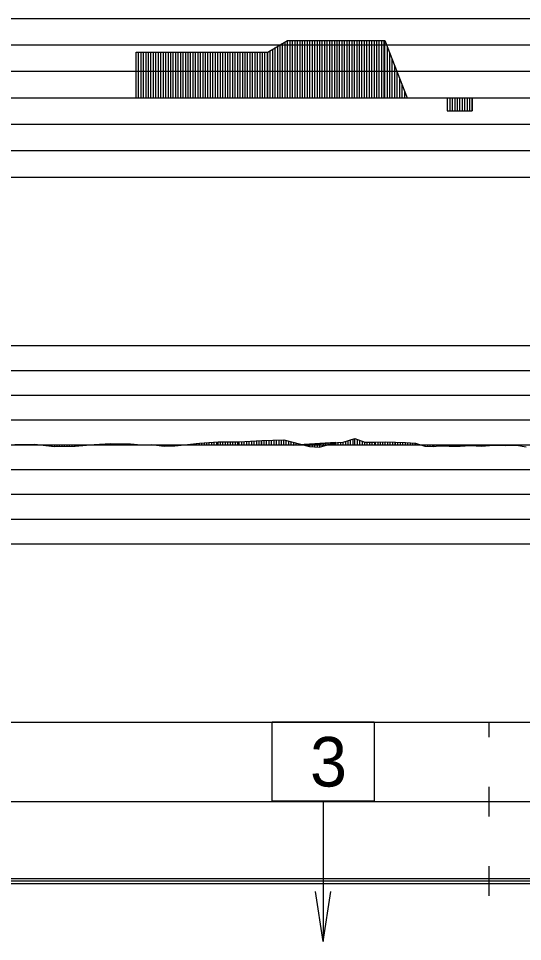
# Model space of a CAD drawing. Extents: x 2 to 10148, y 0 to 380.
# Drawn here: x 1050.8 to 1101.7, y 191.9 to 285 of the extents above; entities that cross this region are included whole.
import ezdxf

# ---------------------------------------------------------------- set-up
doc = ezdxf.new("R2010")
doc.units = 0
for name, color, linetype in [('POSUN_CARA', 7, 'Continuous'), ('POSUN_RASTR', 7, 'Continuous'), ('RYCHL_RASTR', 7, 'Continuous'), ('SLOUPEC', 7, 'Continuous'), ('ZRYCHL_CARA', 7, 'Continuous'), ('ZRYCHL_RASTR', 7, 'Continuous')]:
    doc.layers.add(name, color=color, linetype=linetype)

msp = doc.modelspace()

# ---------------------------------------------------------------- linework, layer by layer
at = {"layer": 'POSUN_CARA'}
for p, q in [((1058.427, 242.028), (1060.09, 242.109)), ((1060.09, 242.109), (1062.119, 242.076)), ((1060.09, 242), (1060.09, 242.109)), ((1060.34, 242), (1060.34, 242.105)), ((1067.549, 242.002), (1069.06, 242.171)), ((1068.549, 242), (1068.549, 242.114)), ((1068.799, 242), (1068.799, 242.142)), ((1069.049, 242), (1069.049, 242.169)), ((1069.06, 242.171), (1070.936, 242.302)), ((1069.06, 242), (1069.06, 242.171)), ((1069.31, 242), (1069.31, 242.188)), ((1069.56, 242), (1069.56, 242.206)), ((1069.81, 242), (1069.81, 242.223)), ((1070.06, 242), (1070.06, 242.241)), ((1070.31, 242), (1070.31, 242.258)), ((1070.56, 242), (1070.56, 242.276)), ((1070.81, 242), (1070.81, 242.293)), ((1070.936, 242.302), (1073.087, 242.304)), ((1070.936, 242), (1070.936, 242.302)), ((1071.186, 242), (1071.186, 242.302)), ((1071.436, 242), (1071.436, 242.302)), ((1071.686, 242), (1071.686, 242.303)), ((1071.936, 242), (1071.936, 242.303)), ((1072.186, 242), (1072.186, 242.303)), ((1072.436, 242), (1072.436, 242.303)), ((1072.686, 242), (1072.686, 242.303)), ((1072.936, 242), (1072.936, 242.304)), ((1073.087, 242.304), (1075.345, 242.428)), ((1073.087, 242), (1073.087, 242.304)), ((1073.337, 242), (1073.337, 242.317)), ((1073.587, 242), (1073.587, 242.331)), ((1073.837, 242), (1073.837, 242.345)), ((1074.087, 242), (1074.087, 242.359)), ((1074.337, 242), (1074.337, 242.373)), ((1074.587, 242), (1074.587, 242.386)), ((1074.837, 242), (1074.837, 242.4)), ((1075.087, 242), (1075.087, 242.414)), ((1075.337, 242), (1075.337, 242.428)), ((1075.345, 242.428), (1077.578, 242.487)), ((1075.345, 242), (1075.345, 242.428)), ((1075.595, 242), (1075.595, 242.435)), ((1075.845, 242), (1075.845, 242.441)), ((1076.095, 242), (1076.095, 242.448)), ((1076.345, 242), (1076.345, 242.454)), ((1076.595, 242), (1076.595, 242.461)), ((1076.845, 242), (1076.845, 242.467)), ((1077.095, 242), (1077.095, 242.474)), ((1077.345, 242), (1077.345, 242.48)), ((1077.578, 242.487), (1080.179, 241.816)), ((1077.578, 242), (1077.578, 242.487)), ((1077.828, 242), (1077.828, 242.422)), ((1078.078, 242), (1078.078, 242.358)), ((1078.328, 242), (1078.328, 242.293)), ((1078.565, 241.959), (1083.569, 242.267)), ((1082.838, 242.237), (1078.565, 241.959)), ((1078.578, 242), (1078.578, 242.229)), ((1078.828, 242), (1078.828, 242.164)), ((1081.065, 242), (1081.065, 242.113)), ((1081.185, 241.754), (1082.838, 242.237)), ((1081.315, 242), (1081.315, 242.128)), ((1081.565, 242), (1081.565, 242.143)), ((1081.815, 242), (1081.815, 242.159)), ((1082.065, 242), (1082.065, 242.174)), ((1082.315, 242), (1082.315, 242.189)), ((1082.435, 242), (1082.435, 242.12)), ((1082.565, 242), (1082.565, 242.205)), ((1082.685, 242), (1082.685, 242.193)), ((1082.815, 242), (1082.815, 242.22)), ((1083.065, 242), (1083.065, 242.236)), ((1083.315, 242), (1083.315, 242.251)), ((1083.565, 242), (1083.565, 242.266)), ((1083.569, 242.267), (1084.747, 242.614)), ((1083.569, 242), (1083.569, 242.267)), ((1083.819, 242), (1083.819, 242.34)), ((1084.069, 242), (1084.069, 242.414)), ((1084.319, 242), (1084.319, 242.487)), ((1084.569, 242), (1084.569, 242.561)), ((1084.747, 242.614), (1085.745, 242.252)), ((1084.747, 242), (1084.747, 242.614)), ((1084.997, 242), (1084.997, 242.523)), ((1085.247, 242), (1085.247, 242.432)), ((1085.497, 242), (1085.497, 242.342)), ((1085.745, 242.252), (1086.828, 242.251)), ((1085.745, 242), (1085.745, 242.252)), ((1085.995, 242), (1085.995, 242.252)), ((1086.245, 242), (1086.245, 242.251)), ((1086.495, 242), (1086.495, 242.251)), ((1086.745, 242), (1086.745, 242.251)), ((1086.828, 242.251), (1087.81, 242.304)), ((1086.828, 242), (1086.828, 242.251)), ((1087.078, 242), (1087.078, 242.265)), ((1087.328, 242), (1087.328, 242.278)), ((1087.578, 242), (1087.578, 242.292)), ((1087.81, 242.304), (1088.84, 242.271)), ((1087.81, 242), (1087.81, 242.304)), ((1088.06, 242), (1088.06, 242.296)), ((1088.31, 242), (1088.31, 242.288)), ((1088.56, 242), (1088.56, 242.28)), ((1088.81, 242), (1088.81, 242.272)), ((1088.84, 242.271), (1089.843, 242.214)), ((1088.84, 242), (1088.84, 242.271)), ((1089.09, 242), (1089.09, 242.257)), ((1089.34, 242), (1089.34, 242.242)), ((1089.59, 242), (1089.59, 242.228)), ((1089.84, 242), (1089.84, 242.214)), ((1089.843, 242.214), (1090.858, 242.156)), ((1089.843, 242), (1089.843, 242.214)), ((1090.093, 242), (1090.093, 242.2)), ((1090.343, 242), (1090.343, 242.185)), ((1090.593, 242), (1090.593, 242.171)), ((1090.843, 242), (1090.843, 242.157)), ((1090.858, 242.156), (1091.812, 241.847)), ((1090.858, 242), (1090.858, 242.156)), ((1050.431, 242.038), (1052.432, 242.05)), ((1050.931, 242), (1050.931, 242.041)), ((1051.181, 242), (1051.181, 242.043)), ((1051.431, 242), (1051.431, 242.044)), ((1051.681, 242), (1051.681, 242.046)), ((1051.931, 242), (1051.931, 242.047)), ((1052.181, 242), (1052.181, 242.049)), ((1052.431, 242), (1052.431, 242.05)), ((1052.432, 242.05), (1054.429, 241.808)), ((1052.432, 242), (1052.432, 242.05)), ((1052.682, 242), (1052.682, 242.02)), ((1052.932, 242), (1052.932, 241.989)), ((1053.182, 242), (1053.182, 241.959)), ((1053.432, 242), (1053.432, 241.929)), ((1053.682, 242), (1053.682, 241.898)), ((1053.932, 242), (1053.932, 241.868)), ((1054.182, 242), (1054.182, 241.838)), ((1054.429, 242), (1054.429, 241.808)), ((1054.429, 241.808), (1056.514, 241.855)), ((1054.679, 242), (1054.679, 241.813)), ((1054.929, 242), (1054.929, 241.819)), ((1055.179, 242), (1055.179, 241.825)), ((1055.429, 242), (1055.429, 241.83)), ((1055.679, 242), (1055.679, 241.836)), ((1055.929, 242), (1055.929, 241.842)), ((1056.179, 242), (1056.179, 241.847)), ((1056.429, 242), (1056.429, 241.853)), ((1056.514, 241.855), (1058.427, 242.028)), ((1056.514, 242), (1056.514, 241.855)), ((1056.764, 242), (1056.764, 241.877)), ((1057.014, 242), (1057.014, 241.9)), ((1057.264, 242), (1057.264, 241.923)), ((1057.514, 242), (1057.514, 241.945)), ((1057.764, 242), (1057.764, 241.968)), ((1058.014, 242), (1058.014, 241.991)), ((1058.264, 242), (1058.264, 242.014)), ((1058.427, 242), (1058.427, 242.028)), ((1058.677, 242), (1058.677, 242.04)), ((1058.927, 242), (1058.927, 242.052)), ((1059.177, 242), (1059.177, 242.065)), ((1059.427, 242), (1059.427, 242.077)), ((1059.677, 242), (1059.677, 242.089)), ((1059.927, 242), (1059.927, 242.101)), ((1060.59, 242), (1060.59, 242.101)), ((1060.84, 242), (1060.84, 242.097)), ((1061.09, 242), (1061.09, 242.093)), ((1061.34, 242), (1061.34, 242.089)), ((1061.59, 242), (1061.59, 242.085)), ((1061.84, 242), (1061.84, 242.081)), ((1062.09, 242), (1062.09, 242.077)), ((1062.119, 242.076), (1063.175, 241.999)), ((1062.119, 242), (1062.119, 242.076)), ((1062.369, 242), (1062.369, 242.058)), ((1062.619, 242), (1062.619, 242.04)), ((1062.869, 242), (1062.869, 242.022)), ((1063.119, 242), (1063.119, 242.004)), ((1063.175, 241.999), (1064.229, 242.037)), ((1063.175, 242), (1063.175, 241.999)), ((1063.425, 242), (1063.425, 242.008)), ((1063.675, 242), (1063.675, 242.017)), ((1063.925, 242), (1063.925, 242.026)), ((1064.175, 242), (1064.175, 242.035)), ((1064.229, 242.037), (1065.502, 241.849)), ((1064.229, 242), (1064.229, 242.037)), ((1064.479, 242), (1064.479, 242)), ((1064.729, 242), (1064.729, 241.963)), ((1064.979, 242), (1064.979, 241.926)), ((1065.229, 242), (1065.229, 241.889)), ((1065.479, 242), (1065.479, 241.852)), ((1065.502, 242), (1065.502, 241.849)), ((1065.502, 241.849), (1066.572, 241.882)), ((1065.752, 242), (1065.752, 241.856)), ((1066.002, 242), (1066.002, 241.864)), ((1066.252, 242), (1066.252, 241.872)), ((1066.502, 242), (1066.502, 241.88)), ((1066.572, 241.882), (1067.549, 242.002)), ((1066.572, 242), (1066.572, 241.882)), ((1066.822, 242), (1066.822, 241.913)), ((1067.072, 242), (1067.072, 241.944)), ((1067.322, 242), (1067.322, 241.974)), ((1067.549, 242), (1067.549, 242.002)), ((1067.799, 242), (1067.799, 242.03)), ((1068.049, 242), (1068.049, 242.058)), ((1068.299, 242), (1068.299, 242.086)), ((1078.565, 242), (1078.565, 241.959)), ((1078.815, 242), (1078.815, 241.974)), ((1079.065, 242), (1079.065, 241.99)), ((1079.078, 242), (1079.078, 242.1)), ((1079.315, 242), (1079.315, 242.005)), ((1079.328, 242), (1079.328, 242.035)), ((1079.565, 242), (1079.565, 242.02)), ((1079.578, 242), (1079.578, 241.971)), ((1079.815, 242), (1079.815, 242.036)), ((1079.828, 242), (1079.828, 241.906)), ((1080.065, 242), (1080.065, 242.051)), ((1080.078, 242), (1080.078, 241.842)), ((1080.179, 242), (1080.179, 241.816)), ((1080.179, 241.816), (1081.185, 241.754)), ((1080.315, 242), (1080.315, 242.067)), ((1080.429, 242), (1080.429, 241.8)), ((1080.565, 242), (1080.565, 242.082)), ((1080.679, 242), (1080.679, 241.785)), ((1080.815, 242), (1080.815, 242.097)), ((1080.929, 242), (1080.929, 241.77)), ((1081.179, 242), (1081.179, 241.755)), ((1081.185, 242), (1081.185, 241.754)), ((1081.435, 242), (1081.435, 241.827)), ((1081.685, 242), (1081.685, 241.9)), ((1081.935, 242), (1081.935, 241.974)), ((1082.185, 242), (1082.185, 242.047)), ((1091.108, 242), (1091.108, 242.075)), ((1091.358, 242), (1091.358, 241.994)), ((1091.608, 242), (1091.608, 241.913)), ((1091.812, 242), (1091.812, 241.847)), ((1091.812, 241.847), (1092.703, 241.806)), ((1092.062, 242), (1092.062, 241.836)), ((1092.312, 242), (1092.312, 241.824)), ((1092.562, 242), (1092.562, 241.813)), ((1092.703, 242), (1092.703, 241.806)), ((1092.703, 241.806), (1093.21, 241.884)), ((1092.953, 242), (1092.953, 241.845)), ((1093.203, 242), (1093.203, 241.883)), ((1093.21, 242), (1093.21, 241.884)), ((1093.21, 241.884), (1094.257, 241.861)), ((1093.46, 242), (1093.46, 241.879)), ((1093.71, 242), (1093.71, 241.873)), ((1093.96, 242), (1093.96, 241.867)), ((1094.21, 242), (1094.21, 241.862)), ((1094.257, 242), (1094.257, 241.861)), ((1094.257, 241.861), (1095.362, 241.838)), ((1094.507, 242), (1094.507, 241.855)), ((1094.757, 242), (1094.757, 241.85)), ((1095.007, 242), (1095.007, 241.845)), ((1095.257, 242), (1095.257, 241.84)), ((1095.362, 242), (1095.362, 241.838)), ((1095.362, 241.838), (1096.402, 241.924)), ((1095.612, 242), (1095.612, 241.858)), ((1095.862, 242), (1095.862, 241.879)), ((1096.112, 242), (1096.112, 241.9)), ((1096.362, 242), (1096.362, 241.921)), ((1096.402, 242), (1096.402, 241.924)), ((1096.402, 241.924), (1097.541, 241.856)), ((1096.652, 242), (1096.652, 241.909)), ((1096.902, 242), (1096.902, 241.894)), ((1097.152, 242), (1097.152, 241.879)), ((1097.402, 242), (1097.402, 241.865)), ((1097.541, 242), (1097.541, 241.856)), ((1097.541, 241.856), (1098.683, 241.944)), ((1097.791, 242), (1097.791, 241.875)), ((1098.041, 242), (1098.041, 241.895)), ((1098.291, 242), (1098.291, 241.914)), ((1098.541, 242), (1098.541, 241.933)), ((1098.683, 242), (1098.683, 241.944)), ((1098.683, 241.944), (1099.905, 241.931)), ((1098.933, 242), (1098.933, 241.941)), ((1099.183, 242), (1099.183, 241.939)), ((1099.433, 242), (1099.433, 241.936)), ((1099.683, 242), (1099.683, 241.934)), ((1099.905, 242), (1099.905, 241.931)), ((1099.905, 241.931), (1101.034, 241.948)), ((1100.155, 242), (1100.155, 241.935)), ((1100.405, 242), (1100.405, 241.939)), ((1100.655, 242), (1100.655, 241.943)), ((1100.905, 242), (1100.905, 241.946)), ((1101.034, 242), (1101.034, 241.948)), ((1101.034, 241.948), (1102.035, 241.788)), ((1101.284, 242), (1101.284, 241.908)), ((1101.534, 242), (1101.534, 241.868))]:
    msp.add_line(p, q, dxfattribs=at)
at = {"layer": 'POSUN_RASTR'}
for p, q in [((952, 252), (1148, 252)), ((952, 249.5), (1148, 249.5)), ((952, 247), (1148, 247)), ((952, 244.5), (1148, 244.5)), ((631.22, 242), (1245.395, 242)), ((952, 239.5), (1148, 239.5)), ((952, 237), (1148, 237)), ((952, 234.5), (1148, 234.5)), ((952, 232), (1148, 232))]:
    msp.add_line(p, q, dxfattribs=at)
at = {"layer": 'RYCHL_RASTR'}
for p, q in [((631.22, 214), (1245.395, 214)), ((1098.288, 212.5), (1098.288, 214)), ((1098.288, 204.5), (1098.288, 207.5)), ((631.22, 206), (1245.395, 206)), ((1098.288, 196.5), (1098.288, 199.5)), ((631.22, 198.25), (1245.395, 198.25)), ((631.22, 198), (1245.395, 198)), ((631.22, 197.75), (1245.395, 197.75))]:
    msp.add_line(p, q, dxfattribs=at)
at = {"layer": 'SLOUPEC'}
for p, q in [((1081.55, 206.034), (1081.55, 191.884)), ((1081.55, 191.884), (1080.783, 196.926)), ((1081.55, 191.884), (1082.318, 196.926))]:
    msp.add_line(p, q, dxfattribs=at)
msp.add_lwpolyline([(1076.404, 214.033), (1086.696, 214.033), (1086.696, 206.034), (1076.404, 206.034)], close=True, dxfattribs=at)
at = {"layer": 'ZRYCHL_CARA'}
for p, q in [((1075.959, 281.615), (1077.959, 282.791)), ((1076.959, 277), (1076.959, 282.203)), ((1077.209, 277), (1077.209, 282.35)), ((1077.459, 277), (1077.459, 282.497)), ((1077.709, 277), (1077.709, 282.644)), ((1077.959, 277), (1077.959, 282.791)), ((1077.959, 282.791), (1087.771, 282.791)), ((1078.209, 277), (1078.209, 282.791)), ((1078.459, 277), (1078.459, 282.791)), ((1078.709, 277), (1078.709, 282.791)), ((1078.959, 277), (1078.959, 282.791)), ((1079.209, 277), (1079.209, 282.791)), ((1079.459, 277), (1079.459, 282.791)), ((1079.709, 277), (1079.709, 282.791)), ((1079.959, 277), (1079.959, 282.791)), ((1080.209, 277), (1080.209, 282.791)), ((1080.459, 277), (1080.459, 282.791)), ((1080.709, 277), (1080.709, 282.791)), ((1080.959, 277), (1080.959, 282.791)), ((1081.209, 277), (1081.209, 282.791)), ((1081.459, 277), (1081.459, 282.791)), ((1081.709, 277), (1081.709, 282.791)), ((1081.959, 277), (1081.959, 282.791)), ((1082.209, 277), (1082.209, 282.791)), ((1082.459, 277), (1082.459, 282.791)), ((1082.709, 277), (1082.709, 282.791)), ((1082.959, 277), (1082.959, 282.791)), ((1083.209, 277), (1083.209, 282.791)), ((1083.459, 277), (1083.459, 282.791)), ((1083.709, 277), (1083.709, 282.791)), ((1083.959, 277), (1083.959, 282.791)), ((1084.209, 277), (1084.209, 282.791)), ((1084.459, 277), (1084.459, 282.791)), ((1084.709, 277), (1084.709, 282.791)), ((1084.959, 277), (1084.959, 282.791)), ((1085.209, 277), (1085.209, 282.791)), ((1085.459, 277), (1085.459, 282.791)), ((1085.709, 277), (1085.709, 282.791)), ((1085.959, 277), (1085.959, 282.791)), ((1086.209, 277), (1086.209, 282.791)), ((1086.459, 277), (1086.459, 282.791)), ((1086.709, 277), (1086.709, 282.791)), ((1086.959, 277), (1086.959, 282.791)), ((1087.209, 277), (1087.209, 282.791)), ((1087.459, 277), (1087.459, 282.791)), ((1087.709, 277), (1087.709, 282.791)), ((1087.771, 277), (1087.771, 282.791)), ((1087.771, 282.791), (1090.017, 277)), ((1088.021, 277), (1088.021, 282.146)), ((1062.676, 277), (1062.676, 281.615)), ((1062.676, 277), (1062.676, 281.615)), ((1062.676, 281.615), (1075.959, 281.615)), ((1062.926, 277), (1062.926, 281.615)), ((1063.176, 277), (1063.176, 281.615)), ((1063.426, 277), (1063.426, 281.615)), ((1063.676, 277), (1063.676, 281.615)), ((1063.926, 277), (1063.926, 281.615)), ((1064.176, 277), (1064.176, 281.615)), ((1064.426, 277), (1064.426, 281.615)), ((1064.676, 277), (1064.676, 281.615)), ((1064.926, 277), (1064.926, 281.615)), ((1065.176, 277), (1065.176, 281.615)), ((1065.426, 277), (1065.426, 281.615)), ((1065.676, 277), (1065.676, 281.615)), ((1065.926, 277), (1065.926, 281.615)), ((1066.176, 277), (1066.176, 281.615)), ((1066.426, 277), (1066.426, 281.615)), ((1066.676, 277), (1066.676, 281.615)), ((1066.926, 277), (1066.926, 281.615)), ((1067.176, 277), (1067.176, 281.615)), ((1067.426, 277), (1067.426, 281.615)), ((1067.676, 277), (1067.676, 281.615)), ((1067.926, 277), (1067.926, 281.615)), ((1068.176, 277), (1068.176, 281.615)), ((1068.426, 277), (1068.426, 281.615)), ((1068.676, 277), (1068.676, 281.615)), ((1068.926, 277), (1068.926, 281.615)), ((1069.176, 277), (1069.176, 281.615)), ((1069.426, 277), (1069.426, 281.615)), ((1069.676, 277), (1069.676, 281.615)), ((1069.926, 277), (1069.926, 281.615)), ((1070.176, 277), (1070.176, 281.615)), ((1070.426, 277), (1070.426, 281.615)), ((1070.676, 277), (1070.676, 281.615)), ((1070.926, 277), (1070.926, 281.615)), ((1071.176, 277), (1071.176, 281.615)), ((1071.426, 277), (1071.426, 281.615)), ((1071.676, 277), (1071.676, 281.615)), ((1071.926, 277), (1071.926, 281.615)), ((1072.176, 277), (1072.176, 281.615)), ((1072.426, 277), (1072.426, 281.615)), ((1072.676, 277), (1072.676, 281.615)), ((1072.926, 277), (1072.926, 281.615)), ((1073.176, 277), (1073.176, 281.615)), ((1073.426, 277), (1073.426, 281.615)), ((1073.676, 277), (1073.676, 281.615)), ((1073.926, 277), (1073.926, 281.615)), ((1074.176, 277), (1074.176, 281.615)), ((1074.426, 277), (1074.426, 281.615)), ((1074.676, 277), (1074.676, 281.615)), ((1074.926, 277), (1074.926, 281.615)), ((1075.176, 277), (1075.176, 281.615)), ((1075.426, 277), (1075.426, 281.615)), ((1075.676, 277), (1075.676, 281.615)), ((1075.926, 277), (1075.926, 281.615)), ((1075.959, 277), (1075.959, 281.615)), ((1076.209, 277), (1076.209, 281.762)), ((1076.459, 277), (1076.459, 281.909)), ((1076.709, 277), (1076.709, 282.056)), ((1088.271, 277), (1088.271, 281.502)), ((1088.521, 277), (1088.521, 280.857)), ((1088.771, 277), (1088.771, 280.212)), ((1089.021, 277), (1089.021, 279.568)), ((1089.271, 277), (1089.271, 278.923)), ((1089.521, 277), (1089.521, 278.278)), ((1089.771, 277), (1089.771, 277.634)), ((631.22, 277), (1245.395, 277)), ((1094.063, 277), (1094.063, 275.687)), ((1094.063, 277), (1094.063, 275.687)), ((1094.313, 277), (1094.313, 275.687)), ((1094.563, 277), (1094.563, 275.687)), ((1094.813, 277), (1094.813, 275.687)), ((1095.063, 277), (1095.063, 275.687)), ((1095.313, 277), (1095.313, 275.687)), ((1095.563, 277), (1095.563, 275.687)), ((1095.813, 277), (1095.813, 275.687)), ((1096.063, 277), (1096.063, 275.687)), ((1096.313, 277), (1096.313, 275.687)), ((1096.563, 277), (1096.563, 275.687)), ((1096.569, 275.687), (1096.569, 277)), ((1094.063, 275.687), (1096.569, 275.687))]:
    msp.add_line(p, q, dxfattribs=at)
at = {"layer": 'ZRYCHL_RASTR'}
for p, q in [((952, 285), (1148, 285)), ((952, 282.333), (1148, 282.333)), ((952, 279.667), (1148, 279.667)), ((952, 274.333), (1148, 274.333)), ((952, 271.667), (1148, 271.667)), ((952, 269), (1148, 269))]:
    msp.add_line(p, q, dxfattribs=at)

# ---------------------------------------------------------------- texts
at = {"layer": 'SLOUPEC'}
msp.add_text('3', height=5, dxfattribs=at).set_placement((1080.227, 207.52))

doc.saveas('drawing.dxf')
